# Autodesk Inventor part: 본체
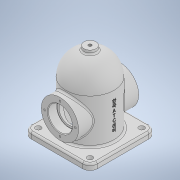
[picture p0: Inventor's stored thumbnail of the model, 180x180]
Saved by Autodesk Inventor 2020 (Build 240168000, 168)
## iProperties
Created: 2021-07
Part Number: 본체
Material: 일반
Document SubType Name: Modeling
Designer: Owner
Mass: 320.706 g
Surface Area: 800.746 cm^2
Volume: 320.706 cm^3
Density: 1 g/cm^3
Appearance: 기본값
Author: Owner
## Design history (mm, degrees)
sketch "스케치1"
  geometry: C1 r 40 at (0, 0); 1 further point
  constraints: 1 centre point, 1 coincident
  dimensions: "d0" = 80 diameter of C1
extrude "돌출1" new body sketch "스케치1" distance "d1" = 124; taper "d2" = 0 deg
fillet "모깎기1" dims "d3" = 40
feature "쉘1" dims "d4" = 8
sketch "스케치2"
  geometry: L1 (55, 55)-(-55, 55); L2 (-55, 55)-(-55, -55); L3 (-55, -55)-(55, -55); L4 (55, -55)-(55, 55); L5 (55, 55)-(-55, -55); L6 (-55, 55)-(55, -55); 1 further point
  constraints: 12 end point, 2 midpoint, 2 parallel, 1 horizontal, 1 perpendicular
  dimensions: "d5" = 110 distance of L3.end L2.end; "d6" = 110 distance of L2.end L1.end
extrude "돌출2" join sketch "스케치2" distance "d7" = 10; taper "d8" = 0 deg
node "작업 평면1"
sketch "스케치3"
  geometry: L1 (-55, 0)-(55, 0) reference; 3 further points
  constraints: 1 midpoint, 1 vertical alignment
  dimensions: "d9" = 48 distance from line of L1 point (0, 48)
sketch "스케치4"
  geometry: C1 r 32 at (0, 0) reference; 1 further point
extrude "돌출3" cut sketch "스케치4" extent not by distance; stored distance "d10" = 114; taper "d11" = 0 deg
node "작업 평면2"
sketch "스케치6"
  geometry: C1 r 31 at (0, 48); 2 further points
  constraints: 1 centre point, 1 coincident
  dimensions: "d13" = 62 diameter of C1
extrude "돌출4" join sketch "스케치6" stored distance "d14" = 10; taper "d15" = 0 deg
sketch "스케치7"
  geometry: C1 r 31 at (0, 0) reference; 2 further points
  constraints: 1 coincident
hole "구멍1" sketch "스케치7" at (0, 0) diameter "d16" = 33; stored, may be unused: countersink angle "d20" = 90 deg, drill point angle "d22" = 0 deg; dims "d17" = 6, "d18" = 40, "d19" = 15, "d21" = 8
fillet "모깎기2" dims "d23" = 0.3
chamfer "모따기1" distance "d24" = 1; stored, may be unused: second distance "d25" = 2, angle "d26" = 45 deg
sketch "스케치8"
  geometry: C1 r 16.5 at (0, 0) reference; 2 further points
  constraints: 1 vertical alignment
  dimensions: "d27" = 25.5 distance of C1.centre point (0, 25.5)
hole "구멍2" sketch "스케치8" at (0, 25.5) diameter "d28" = 3.242; stored, may be unused: countersink angle "d32" = 90 deg, drill point angle "d34" = 118 deg; dims "d29" = 8, "d30" = 40, "d31" = 15, "d33" = 10
fillet "모깎기3" dims "d38" = 12
fillet "모깎기4" dims "d39" = 3
fillet "모깎기5" dims "d40" = 3
sketch "스케치9"
  geometry: A1 r 9 centre (43, -43) between (43, -52) and (52, -43) reference; 2 further points
  constraints: 1 coincident
hole "구멍3" sketch "스케치9" at (43, -43) diameter "d41" = 9; stored, may be unused: countersink angle "d45" = 90 deg, drill point angle "d47" = 118 deg; dims "d42" = 8, "d43" = 40, "d44" = 15, "d46" = 10
node "작업 평면3"
sketch "스케치10"
  geometry: C1 r 10 at (0, 0); 1 further point
  constraints: 1 centre point, 1 coincident
  dimensions: "d49" = 20 diameter of C1
extrude "돌출5" join sketch "스케치10" stored distance "d50" = 10; taper "d51" = 0 deg
sketch "스케치11"
  geometry: C1 r 10 at (0, 0) reference; 2 further points
  constraints: 1 coincident
hole "구멍4" sketch "스케치11" at (0, 0) diameter "d52" = 5.1881; stored, may be unused: countersink angle "d56" = 90 deg, drill point angle "d58" = 0 deg; dims "d53" = 12, "d54" = 40, "d55" = 15, "d57" = 16
fillet "모깎기6" dims "d59" = 3
node "작업 평면4"
sketch "스케치12"
  geometry: L1 (0, 43)-(0, -43) reference; 3 further points
  constraints: 1 horizontal alignment, 1 midpoint, 1 other
  dimensions: "d60" = 48 distance from line of L1 point (48, 0)
feature "엠보싱1" sketch "스케치12" dims "d61" = 0.5, "d62" = 0
node "솔리드1"
mirror "미러1"
pattern_circular "원형 패턴1" dims angle "d36" = 360 deg
mirror "미러2"
mirror "미러3"
mirror "미러4"
node "투영된 루프1"
feature "A9D066F2-1C7D-4E18-AEED-F7BC21143FA4" dims "d16" = 33, "d17" = 6, "d18" = 40, "d19" = 15, "d20" = 90 deg, "d21" = 8, "d22" = 0
other parameters: "d48" = 129
